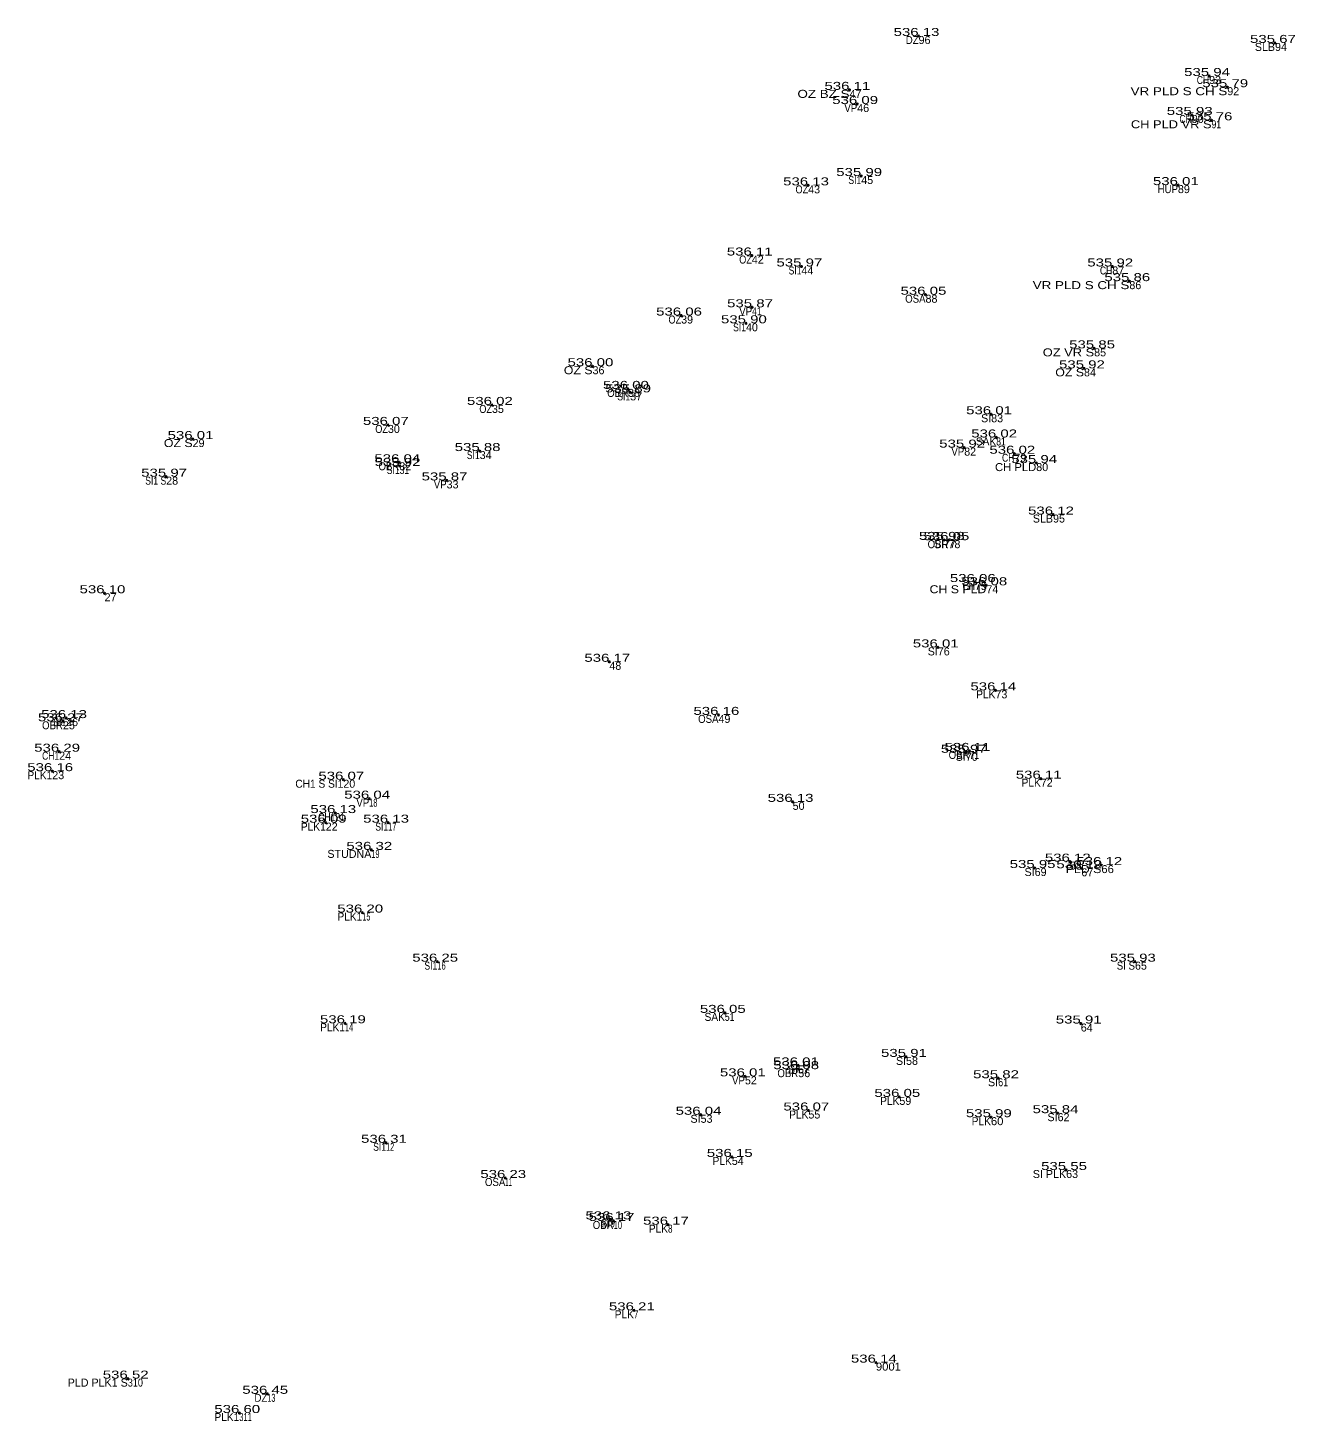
# Model space of a CAD drawing. Extents: x -643086 to -639283, y -1131805 to -1123269.
# Drawn here: x -643019.6 to -642972.1, y -1131461.1 to -1131408.8 of the extents above; entities that cross this region are included whole.
import ezdxf
from ezdxf.enums import TextEntityAlignment as Align

# ---------------------------------------------------------------- set-up
doc = ezdxf.new("R2010")
doc.units = 0
doc.header["$LTSCALE"] = 0.12
doc.header["$PDMODE"] = 32
doc.header["$PDSIZE"] = 0.06
for name, color, linetype in [('1', 7, 'Continuous'), ('2', 7, 'Continuous'), ('3', 7, 'Continuous'), ('4', 7, 'Continuous')]:
    doc.layers.add(name, color=color, linetype=linetype)

msp = doc.modelspace()

# ---------------------------------------------------------------- linework, layer by layer
at = {"layer": '1'}
for p in [(-642986.24, -1131409.15), (-642972.88, -1131409.41), (-642975.35, -1131410.65), (-642974.67, -1131411.07), (-642988.83, -1131411.17), (-642988.54, -1131411.7), (-642976, -1131412.11), (-642975.26, -1131412.31), (-642990.38, -1131414.75), (-642988.39, -1131414.4), (-642976.52, -1131414.74), (-642992.49, -1131417.38), (-642990.63, -1131417.79), (-642978.98, -1131417.79), (-642978.34, -1131418.34), (-642985.98, -1131418.85), (-642992.48, -1131419.32), (-642995.14, -1131419.63), (-642992.71, -1131419.92), (-642979.66, -1131420.86), (-642998.46, -1131421.53), (-642980.04, -1131421.61), (-642997.13, -1131422.38), (-642997.05, -1131422.51), (-643002.23, -1131422.98), (-642983.52, -1131423.33), (-643006.13, -1131423.73), (-642983.33, -1131424.2), (-643013.45, -1131424.26), (-643002.69, -1131424.71), (-642984.53, -1131424.58), (-643005.7, -1131425.13), (-642982.65, -1131424.81), (-642981.83, -1131425.16), (-643014.44, -1131425.67), (-643005.69, -1131425.27), (-643003.93, -1131425.81), (-642981.2, -1131427.09), (-642985.29, -1131428.04), (-642985.12, -1131428.05), (-642984.13, -1131429.62), (-642983.7, -1131429.74), (-643016.75, -1131430.04), (-642985.52, -1131432.07), (-642997.83, -1131432.61), (-642983.36, -1131433.68), (-642993.74, -1131434.6), (-643018.31, -1131434.84), (-643018.19, -1131434.72), (-643018.45, -1131435.98), (-642984.47, -1131436.02), (-642984.33, -1131435.95), (-643018.71, -1131436.71), (-643007.8, -1131437.03), (-642981.66, -1131436.99), (-643006.83, -1131437.74), (-643008.1, -1131438.28), (-642990.96, -1131437.86), (-643008.46, -1131438.64), (-643006.12, -1131438.64), (-643006.75, -1131439.66), (-642981.89, -1131440.34), (-642980.57, -1131440.1), (-642980.14, -1131440.35), (-642979.39, -1131440.23), (-643007.09, -1131442.01), (-643004.28, -1131443.85), (-642978.13, -1131443.85), (-642993.5, -1131445.77), (-643007.74, -1131446.16), (-642980.16, -1131446.17), (-642986.71, -1131447.42), (-642992.75, -1131448.15), (-642990.76, -1131447.74), (-642990.75, -1131447.88), (-642983.26, -1131448.22), (-642986.96, -1131448.92), (-642994.41, -1131449.59), (-642990.37, -1131449.43), (-642983.53, -1131449.68), (-642981.03, -1131449.53), (-643006.2, -1131450.64), (-642993.24, -1131451.17), (-642980.71, -1131451.66), (-643001.73, -1131451.96), (-642997.79, -1131453.51), (-642997.67, -1131453.57), (-642995.63, -1131453.71), (-642996.91, -1131456.92), (-642987.84, -1131458.88), (-643015.88, -1131459.48), (-643010.65, -1131460.05), (-643011.7, -1131460.77)]:
    msp.add_point(p, dxfattribs=at)

# ---------------------------------------------------------------- texts
at = {"layer": '2'}
for s, p in [('96', (-642986.24, -1131409.45)), ('94', (-642972.88, -1131409.71)), ('93', (-642975.35, -1131410.95)), ('92', (-642974.67, -1131411.37)), ('47', (-642988.83, -1131411.47)), ('46', (-642988.54, -1131412)), ('90', (-642976, -1131412.41)), ('43', (-642990.38, -1131415.05)), ('45', (-642988.39, -1131414.7)), ('89', (-642976.52, -1131415.04)), ('42', (-642992.49, -1131417.68)), ('44', (-642990.63, -1131418.09)), ('87', (-642978.98, -1131418.09)), ('86', (-642978.34, -1131418.64)), ('88', (-642985.98, -1131419.15)), ('39', (-642995.14, -1131419.93)), ('40', (-642992.71, -1131420.22)), ('85', (-642979.66, -1131421.16)), ('36', (-642998.46, -1131421.83)), ('84', (-642980.04, -1131421.91)), ('38', (-642997.13, -1131422.68)), ('37', (-642997.05, -1131422.81)), ('35', (-643002.23, -1131423.28)), ('83', (-642983.52, -1131423.63)), ('30', (-643006.13, -1131424.03)), ('29', (-643013.45, -1131424.56)), ('82', (-642984.53, -1131424.88)), ('32', (-643005.7, -1131425.43)), ('34', (-643002.69, -1131425.01)), ('79', (-642982.65, -1131425.11)), ('80', (-642981.83, -1131425.46)), ('28', (-643014.44, -1131425.97)), ('33', (-643003.93, -1131426.11)), ('95', (-642981.2, -1131427.39)), ('77', (-642985.29, -1131428.34)), ('78', (-642985.12, -1131428.35)), ('75', (-642984.13, -1131429.92)), ('74', (-642983.7, -1131430.04)), ('27', (-643016.75, -1131430.34)), ('76', (-642985.52, -1131432.37)), ('48', (-642997.83, -1131432.91)), ('73', (-642983.36, -1131433.98)), ('49', (-642993.74, -1131434.9)), ('25', (-643018.31, -1131435.14)), ('26', (-643018.19, -1131435.02)), ('24', (-643018.45, -1131436.28)), ('70', (-642984.47, -1131436.32)), ('23', (-643018.71, -1131437.01)), ('20', (-643007.8, -1131437.33)), ('72', (-642981.66, -1131437.29)), ('50', (-642990.96, -1131438.16)), ('22', (-643008.46, -1131438.94)), ('69', (-642981.89, -1131440.64)), ('68', (-642980.57, -1131440.4)), ('67', (-642980.14, -1131440.65)), ('65', (-642978.13, -1131444.15)), ('64', (-642980.16, -1131446.47)), ('58', (-642986.71, -1131447.72)), ('52', (-642992.75, -1131448.45)), ('57', (-642990.76, -1131448.04)), ('56', (-642990.75, -1131448.18)), ('59', (-642986.96, -1131449.22)), ('53', (-642994.41, -1131449.89)), ('55', (-642990.37, -1131449.73)), ('62', (-642981.03, -1131449.83)), ('54', (-642993.24, -1131451.47)), ('63', (-642980.71, -1131451.96))]:
    msp.add_text(s, height=0.3, dxfattribs=at).set_placement(p)
for s, width, p in [('91', 0.8, (-642975.26, -1131412.61)), ('41', 0.8, (-642992.48, -1131419.62)), ('81', 0.8, (-642983.33, -1131424.5)), ('31', 0.8, (-643005.69, -1131425.57)), ('71', 0.8, (-642984.33, -1131436.25)), ('18', 0.6, (-643006.83, -1131438.04)), ('21', 0.8, (-643008.1, -1131438.58)), ('17', 0.6, (-643006.12, -1131438.94)), ('19', 0.6, (-643006.75, -1131439.96)), ('66', 1.05, (-642979.39, -1131440.53)), ('15', 0.6, (-643007.09, -1131442.31)), ('16', 0.65, (-643004.28, -1131444.15)), ('51', 0.8, (-642993.5, -1131446.07)), ('14', 0.6, (-643007.74, -1131446.46)), ('61', 0.85, (-642983.26, -1131448.52)), ('60', 1.05, (-642983.53, -1131449.98)), ('12', 0.6, (-643006.2, -1131450.94)), ('11', 0.45, (-643001.73, -1131452.26)), ('9', 0.75, (-642997.79, -1131453.81)), ('10', 0.65, (-642997.67, -1131453.87)), ('8', 0.75, (-642995.63, -1131454.01)), ('7', 0.75, (-642996.91, -1131457.22)), ('9001', 1.05, (-642987.84, -1131459.18)), ('310', 0.85, (-643015.88, -1131459.78)), ('13', 0.6, (-643010.65, -1131460.35)), ('311', 0.7, (-643011.7, -1131461.07))]:
    msp.add_text(s, height=0.3, dxfattribs=dict(at, width=width)).set_placement(p)
at = {"layer": '3', "width": 1.4}
for s, p in [('536 13 ', (-642986.24, -1131409.15)), ('535 67 ', (-642972.88, -1131409.41)), ('535 94 ', (-642975.35, -1131410.65)), ('536 11 ', (-642988.83, -1131411.17)), ('535 79 ', (-642974.67, -1131411.07)), ('536 09 ', (-642988.54, -1131411.7)), ('535 93 ', (-642976, -1131412.11)), ('535 76 ', (-642975.26, -1131412.31)), ('535 99 ', (-642988.39, -1131414.4)), ('536 13 ', (-642990.38, -1131414.75)), ('536 01 ', (-642976.52, -1131414.74)), ('536 11 ', (-642992.49, -1131417.38)), ('535 97 ', (-642990.63, -1131417.79)), ('535 92 ', (-642978.98, -1131417.79)), ('535 86 ', (-642978.34, -1131418.34)), ('536 05 ', (-642985.98, -1131418.85)), ('536 06 ', (-642995.14, -1131419.63)), ('535 87 ', (-642992.48, -1131419.32)), ('535 90 ', (-642992.71, -1131419.92)), ('535 85 ', (-642979.66, -1131420.86)), ('536 00 ', (-642998.46, -1131421.53)), ('535 92 ', (-642980.04, -1131421.61)), ('536 00 ', (-642997.13, -1131422.38)), ('535 89 ', (-642997.05, -1131422.51)), ('536 02 ', (-643002.23, -1131422.98)), ('536 01 ', (-642983.52, -1131423.33)), ('536 07 ', (-643006.13, -1131423.73)), ('536 01 ', (-643013.45, -1131424.26)), ('536 02 ', (-642983.33, -1131424.2)), ('535 88 ', (-643002.69, -1131424.71)), ('535 92 ', (-642984.53, -1131424.58)), ('536 02 ', (-642982.65, -1131424.81)), ('536 04 ', (-643005.7, -1131425.13)), ('535 92 ', (-643005.69, -1131425.27)), ('535 94 ', (-642981.83, -1131425.16)), ('535 97 ', (-643014.44, -1131425.67)), ('535 87 ', (-643003.93, -1131425.81)), ('536 12 ', (-642981.2, -1131427.09)), ('535 98 ', (-642985.29, -1131428.04)), ('536 05 ', (-642985.12, -1131428.05)), ('536 06 ', (-642984.13, -1131429.62)), ('536 10 ', (-643016.75, -1131430.04)), ('536 08 ', (-642983.7, -1131429.74)), ('536 01 ', (-642985.52, -1131432.07)), ('536 17 ', (-642997.83, -1131432.61)), ('536 14 ', (-642983.36, -1131433.68)), ('536 27 ', (-643018.31, -1131434.84)), ('536 13 ', (-643018.19, -1131434.72)), ('536 16 ', (-642993.74, -1131434.6)), ('536 11 ', (-642984.33, -1131435.95)), ('536 29 ', (-643018.45, -1131435.98)), ('535 97 ', (-642984.47, -1131436.02)), ('536 16 ', (-643018.71, -1131436.71)), ('536 11 ', (-642981.66, -1131436.99)), ('536 07 ', (-643007.8, -1131437.03)), ('536 04 ', (-643006.83, -1131437.74)), ('536 13 ', (-642990.96, -1131437.86)), ('536 13 ', (-643008.1, -1131438.28)), ('536 09 ', (-643008.46, -1131438.64)), ('536 13 ', (-643006.12, -1131438.64)), ('536 32 ', (-643006.75, -1131439.66)), ('536 12 ', (-642980.57, -1131440.1)), ('535 95 ', (-642981.89, -1131440.34)), ('536 12 ', (-642980.14, -1131440.35)), ('536 12 ', (-642979.39, -1131440.23)), ('536 20 ', (-643007.09, -1131442.01)), ('536 25 ', (-643004.28, -1131443.85)), ('535 93 ', (-642978.13, -1131443.85)), ('536 05 ', (-642993.5, -1131445.77)), ('536 19 ', (-643007.74, -1131446.16)), ('535 91 ', (-642980.16, -1131446.17)), ('535 91 ', (-642986.71, -1131447.42)), ('536 01 ', (-642990.76, -1131447.74)), ('536 08 ', (-642990.75, -1131447.88)), ('536 01 ', (-642992.75, -1131448.15)), ('535 82 ', (-642983.26, -1131448.22)), ('536 05 ', (-642986.96, -1131448.92)), ('536 07 ', (-642990.37, -1131449.43)), ('535 84 ', (-642981.03, -1131449.53)), ('536 04 ', (-642994.41, -1131449.59)), ('535 99 ', (-642983.53, -1131449.68)), ('536 31 ', (-643006.2, -1131450.64)), ('536 15 ', (-642993.24, -1131451.17)), ('536 23 ', (-643001.73, -1131451.96)), ('535 55 ', (-642980.71, -1131451.66)), ('536 13 ', (-642997.79, -1131453.51)), ('536 17 ', (-642997.67, -1131453.57)), ('536 17 ', (-642995.63, -1131453.71)), ('536 21 ', (-642996.91, -1131456.92)), ('536 14 ', (-642987.84, -1131458.88)), ('536 52 ', (-643015.88, -1131459.48)), ('536 45 ', (-643010.65, -1131460.05)), ('536 60 ', (-643011.7, -1131460.77))]:
    msp.add_text(s, height=0.3, dxfattribs=at).set_placement(p, align=Align.CENTER)
at = {"layer": '4'}
for s, width, p in [('DZ', 0.9, (-642986.24, -1131409.45)), ('VR PLD S CH S', 1.25, (-642974.67, -1131411.37)), ('CH', 0.8, (-642975.35, -1131410.95)), ('OZ BZ S', 1.25, (-642988.83, -1131411.47)), ('VP', 0.9, (-642988.54, -1131412)), ('CH', 0.8, (-642976, -1131412.41)), ('CH PLD VR S', 1.2, (-642975.26, -1131412.61)), ('OZ', 0.85, (-642990.38, -1131415.05)), ('SI1', 0.8, (-642988.39, -1131414.7)), ('HUP', 0.9, (-642976.52, -1131415.04)), ('OZ', 0.85, (-642992.49, -1131417.68)), ('SI1', 0.8, (-642990.63, -1131418.09)), ('CH', 0.8, (-642978.98, -1131418.09)), ('VR PLD S CH S', 1.25, (-642978.34, -1131418.64)), ('OSA', 0.9, (-642985.98, -1131419.15)), ('VP', 0.9, (-642992.48, -1131419.62)), ('OZ', 0.85, (-642995.14, -1131419.93)), ('SI1', 0.8, (-642992.71, -1131420.22)), ('OZ VR S', 1.2, (-642979.66, -1131421.16)), ('OZ S', 1.15, (-642998.46, -1131421.83)), ('OZ S', 1.15, (-642980.04, -1131421.91)), ('OBR', 0.9, (-642997.13, -1131422.68)), ('SI1', 0.8, (-642997.05, -1131422.81)), ('OZ', 0.85, (-643002.23, -1131423.28)), ('OZ', 0.85, (-643006.13, -1131424.03)), ('OZ S', 1.15, (-643013.45, -1131424.56)), ('VP', 0.9, (-642984.53, -1131424.88)), ('SAK', 0.95, (-642983.33, -1131424.5)), ('OBR', 0.9, (-643005.7, -1131425.43)), ('SI1', 0.8, (-643002.69, -1131425.01)), ('CH PLD', 1.05, (-642981.83, -1131425.46)), ('CH', 0.8, (-642982.65, -1131425.11)), ('SI1 S', 0.8, (-643014.44, -1131425.97)), ('SI1', 0.8, (-643005.69, -1131425.57)), ('VP', 0.9, (-643003.93, -1131426.11)), ('OBR', 0.9, (-642985.12, -1131428.35)), ('CH S PLD', 1.15, (-642983.7, -1131430.04)), ('CH', 0.8, (-642984.13, -1131429.92)), ('PLK', 0.95, (-642983.36, -1131433.98)), ('OSA', 0.9, (-642993.74, -1131434.9)), ('OBR', 0.9, (-643018.31, -1131435.14)), ('SI1', 0.8, (-643018.19, -1131435.02)), ('CH1', 0.8, (-643018.45, -1131436.28)), ('OBR', 0.9, (-642984.33, -1131436.25)), ('PLK1', 0.95, (-643018.71, -1131437.01)), ('CH1 S SI1', 0.95, (-643007.8, -1131437.33)), ('PLK', 0.95, (-642981.66, -1131437.29)), ('VP', 0.9, (-643006.83, -1131438.04)), ('CH1', 0.8, (-643008.1, -1131438.58)), ('PLK1', 0.95, (-643008.46, -1131438.94)), ('SI1', 0.8, (-643006.12, -1131438.94)), ('PLD S', 1.15, (-642979.39, -1131440.53)), ('PLK1', 0.95, (-643007.09, -1131442.31)), ('SI1', 0.8, (-643004.28, -1131444.15)), ('SI S', 0.9, (-642978.13, -1131444.15)), ('SAK', 0.95, (-642993.5, -1131446.07)), ('PLK1', 0.95, (-643007.74, -1131446.46)), ('VP', 0.9, (-642992.75, -1131448.45)), ('OBR', 0.9, (-642990.75, -1131448.18)), ('PLK', 0.95, (-642986.96, -1131449.22)), ('PLK', 0.95, (-642990.37, -1131449.73)), ('PLK', 0.95, (-642983.53, -1131449.98)), ('SI1', 0.8, (-643006.2, -1131450.94)), ('PLK', 0.95, (-642993.24, -1131451.47)), ('OSA', 0.9, (-643001.73, -1131452.26)), ('OBR', 0.9, (-642997.67, -1131453.87)), ('PLK', 0.95, (-642995.63, -1131454.01)), ('PLK', 0.95, (-642996.91, -1131457.22)), ('DZ', 0.9, (-643010.65, -1131460.35)), ('PLK1', 0.95, (-643011.7, -1131461.07))]:
    msp.add_text(s, height=0.3, dxfattribs=dict(at, width=width)).set_placement(p, align=Align.RIGHT)
for s, p in [('SLB', (-642972.88, -1131409.71)), ('SI', (-642983.52, -1131423.63)), ('SLB', (-642981.2, -1131427.39)), ('SI', (-642985.29, -1131428.34)), ('SI', (-642985.52, -1131432.37)), ('SI', (-642984.47, -1131436.32)), ('STUDNA', (-643006.75, -1131439.96)), ('SI', (-642981.89, -1131440.64)), ('SI', (-642986.71, -1131447.72)), ('SI', (-642990.76, -1131448.04)), ('SI', (-642983.26, -1131448.52)), ('SI', (-642994.41, -1131449.89)), ('SI', (-642981.03, -1131449.83)), ('SI PLK', (-642980.71, -1131451.96)), ('SI', (-642997.79, -1131453.81)), ('PLD PLK1 S', (-643015.88, -1131459.78))]:
    msp.add_text(s, height=0.3, dxfattribs=at).set_placement(p, align=Align.RIGHT)

doc.saveas('drawing.dxf')
